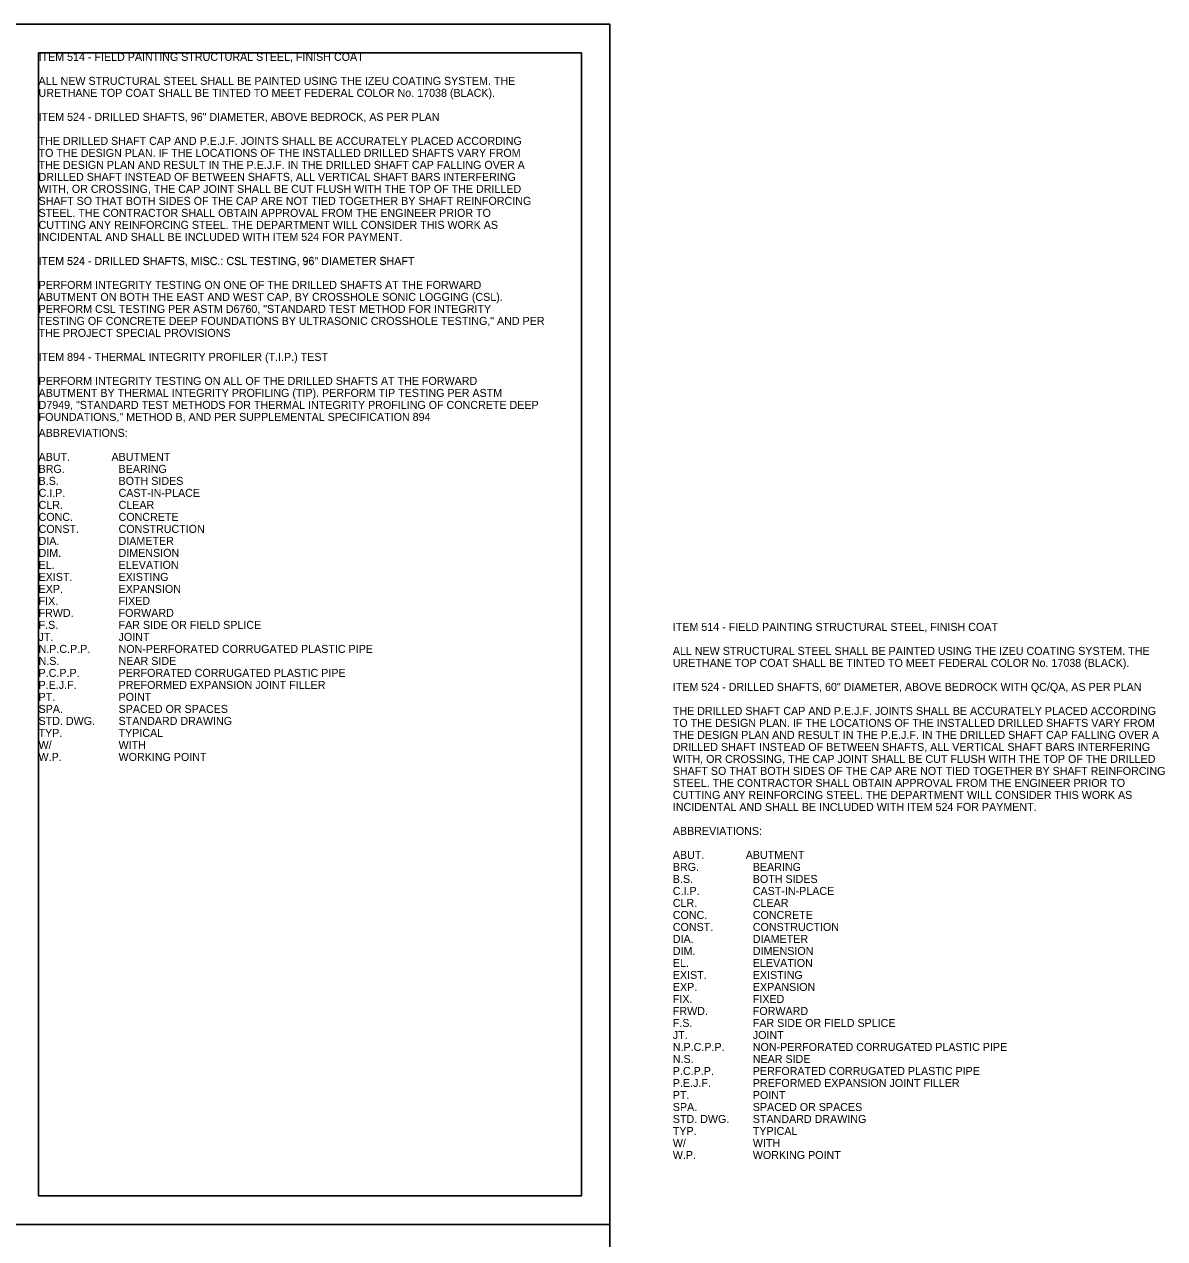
# Model space of a CAD drawing. Extents: x -27.4 to 41.5, y -43.2 to 24.4.
# Drawn here: x 21.49 to 41.45, y -1.99 to 19.26 of the extents above; entities that cross this region are included whole.
import ezdxf

# ---------------------------------------------------------------- set-up
doc = ezdxf.new("R2010")
doc.units = 0
for name, color, linetype in [('BR_P_Slab_Object', 7, 'Continuous'), ('BR_P_Sub_Foot_Hidden', 7, 'Continuous'), ('Default', 7, 'Continuous'), ('SH_Data', 7, 'Continuous')]:
    doc.layers.add(name, color=color, linetype=linetype)

msp = doc.modelspace()

# ---------------------------------------------------------------- linework, layer by layer
at = {"layer": 'BR_P_Slab_Object'}
msp.add_lwpolyline([(21.744, 18.759), (31.244, 18.759), (31.244, -1.241), (21.744, -1.241)], close=True, dxfattribs=at)
at = {"layer": 'SH_Data'}
for points in [[(1.244, 19.259), (31.744, 19.259), (31.744, -1.741), (1.244, -1.741)], [(1.244, -1.741), (31.744, -1.741), (31.744, -22.741), (1.244, -22.741)]]:
    msp.add_lwpolyline(points, close=True, dxfattribs=at)

# ---------------------------------------------------------------- texts
at = {"layer": 'BR_P_Sub_Foot_Hidden'}
for s, p in [('ITEM 514 - FIELD PAINTING STRUCTURAL STEEL, FINISH COAT', (21.744, 18.619)), ('ITEM 514 - FIELD PAINTING STRUCTURAL STEEL, FINISH COAT', (21.744, 18.619)), ('ALL NEW STRUCTURAL STEEL SHALL BE PAINTED USING THE IZEU COATING SYSTEM. THE ', (21.744, 18.199)), ('URETHANE TOP COAT SHALL BE TINTED TO MEET FEDERAL COLOR No. 17038 (BLACK).', (21.744, 17.989)), ('ITEM 524 - DRILLED SHAFTS, 96" DIAMETER, ABOVE BEDROCK, AS PER PLAN', (21.744, 17.569)), ('ITEM 524 - DRILLED SHAFTS, 96" DIAMETER, ABOVE BEDROCK, AS PER PLAN', (21.744, 17.569)), ('THE DRILLED SHAFT CAP AND P.E.J.F. JOINTS SHALL BE ACCURATELY PLACED ACCORDING ', (21.744, 17.149)), ('TO THE DESIGN PLAN. IF THE LOCATIONS OF THE INSTALLED DRILLED SHAFTS VARY FROM ', (21.744, 16.939)), ('THE DESIGN PLAN AND RESULT IN THE P.E.J.F. IN THE DRILLED SHAFT CAP FALLING OVER A ', (21.744, 16.729)), ('DRILLED SHAFT INSTEAD OF BETWEEN SHAFTS, ALL VERTICAL SHAFT BARS INTERFERING ', (21.744, 16.519)), ('WITH, OR CROSSING, THE CAP JOINT SHALL BE CUT FLUSH WITH THE TOP OF THE DRILLED ', (21.744, 16.309)), ('SHAFT SO THAT BOTH SIDES OF THE CAP ARE NOT TIED TOGETHER BY SHAFT REINFORCING ', (21.744, 16.099)), ('STEEL. THE CONTRACTOR SHALL OBTAIN APPROVAL FROM THE ENGINEER PRIOR TO ', (21.744, 15.889)), ('CUTTING ANY REINFORCING STEEL. THE DEPARTMENT WILL CONSIDER THIS WORK AS ', (21.744, 15.679)), ('INCIDENTAL AND SHALL BE INCLUDED WITH ITEM 524 FOR PAYMENT.', (21.744, 15.469)), ('ITEM 524 - DRILLED SHAFTS, MISC.: CSL TESTING, 96" DIAMETER SHAFT ', (21.744, 15.049)), ('PERFORM INTEGRITY TESTING ON ONE OF THE DRILLED SHAFTS AT THE FORWARD ', (21.744, 14.629)), ('ABUTMENT ON BOTH THE EAST AND WEST CAP, BY CROSSHOLE SONIC LOGGING (CSL). ', (21.744, 14.419)), ('PERFORM CSL TESTING PER ASTM D6760, "STANDARD TEST METHOD FOR INTEGRITY ', (21.744, 14.209)), ('TESTING OF CONCRETE DEEP FOUNDATIONS BY ULTRASONIC CROSSHOLE TESTING," AND PER ', (21.744, 13.999)), ('THE PROJECT SPECIAL PROVISIONS', (21.744, 13.789)), ('ITEM 894 - THERMAL INTEGRITY PROFILER (T.I.P.) TEST ', (21.744, 13.369)), ('PERFORM INTEGRITY TESTING ON ALL OF THE DRILLED SHAFTS AT THE FORWARD ', (21.744, 12.949)), ('ABUTMENT BY THERMAL INTEGRITY PROFILING (TIP). PERFORM TIP TESTING PER ASTM ', (21.744, 12.739)), ('D7949, "STANDARD TEST METHODS FOR THERMAL INTEGRITY PROFILING OF CONCRETE DEEP ', (21.744, 12.529)), ('FOUNDATIONS," METHOD B, AND PER SUPPLEMENTAL SPECIFICATION 894', (21.744, 12.319)), ('ABBREVIATIONS:', (21.744, 12.04)), ('ABUT.', (21.744, 11.62)), ('   ABUTMENT', (22.864, 11.62)), ('BRG.', (21.744, 11.41)), ('BEARING', (23.144, 11.41)), ('B.S.', (21.744, 11.2)), ('BOTH SIDES', (23.144, 11.2)), ('C.I.P.', (21.744, 10.99)), ('CAST-IN-PLACE', (23.144, 10.99)), ('CLR.', (21.744, 10.78)), ('CLEAR', (23.144, 10.78)), ('CONC.', (21.744, 10.57)), ('CONCRETE', (23.144, 10.57)), ('CONST. ', (21.744, 10.36)), ('CONSTRUCTION', (23.144, 10.36)), ('DIA.', (21.744, 10.15)), ('DIAMETER', (23.144, 10.15)), ('DIM.', (21.744, 9.94)), ('DIMENSION', (23.144, 9.94)), ('EL.', (21.744, 9.73)), ('ELEVATION', (23.144, 9.73)), ('EXIST.', (21.744, 9.52)), ('EXISTING', (23.144, 9.52)), ('EXP.', (21.744, 9.31)), ('EXPANSION', (23.144, 9.31)), ('FIX.', (21.744, 9.1)), ('FIXED', (23.144, 9.1)), ('FRWD.', (21.744, 8.89)), ('FORWARD', (23.144, 8.89)), ('F.S.', (21.744, 8.68)), ('FAR SIDE OR FIELD SPLICE', (23.144, 8.68)), ('ITEM 514 - FIELD PAINTING STRUCTURAL STEEL, FINISH COAT', (32.844, 8.645)), ('ITEM 514 - FIELD PAINTING STRUCTURAL STEEL, FINISH COAT', (32.844, 8.645)), ('JT.', (21.744, 8.47)), ('JOINT', (23.144, 8.47)), ('N.P.C.P.P.', (21.744, 8.26)), ('NON-PERFORATED CORRUGATED PLASTIC PIPE', (23.144, 8.26)), ('ALL NEW STRUCTURAL STEEL SHALL BE PAINTED USING THE IZEU COATING SYSTEM. THE ', (32.844, 8.225)), ('N.S.', (21.744, 8.05)), ('NEAR SIDE', (23.144, 8.05)), ('URETHANE TOP COAT SHALL BE TINTED TO MEET FEDERAL COLOR No. 17038 (BLACK).', (32.844, 8.015)), ('P.C.P.P.', (21.744, 7.84)), ('PERFORATED CORRUGATED PLASTIC PIPE', (23.144, 7.84)), ('P.E.J.F.', (21.744, 7.63)), ('PREFORMED EXPANSION JOINT FILLER', (23.144, 7.63)), ('ITEM 524 - DRILLED SHAFTS, 60" DIAMETER, ABOVE BEDROCK WITH QC/QA, AS PER PLAN', (32.844, 7.595)), ('ITEM 524 - DRILLED SHAFTS, 60" DIAMETER, ABOVE BEDROCK WITH QC/QA, AS PER PLAN', (32.844, 7.595)), ('PT.', (21.744, 7.42)), ('POINT', (23.144, 7.42)), ('SPA.', (21.744, 7.21)), ('SPACED OR SPACES', (23.144, 7.21)), ('THE DRILLED SHAFT CAP AND P.E.J.F. JOINTS SHALL BE ACCURATELY PLACED ACCORDING ', (32.844, 7.175)), ('STD. DWG.', (21.744, 7)), ('STANDARD DRAWING', (23.144, 7)), ('TO THE DESIGN PLAN. IF THE LOCATIONS OF THE INSTALLED DRILLED SHAFTS VARY FROM ', (32.844, 6.965)), ('TYP.', (21.744, 6.79)), ('TYPICAL', (23.144, 6.79)), ('THE DESIGN PLAN AND RESULT IN THE P.E.J.F. IN THE DRILLED SHAFT CAP FALLING OVER A ', (32.844, 6.755)), ('W/', (21.744, 6.58)), ('WITH', (23.144, 6.58)), ('DRILLED SHAFT INSTEAD OF BETWEEN SHAFTS, ALL VERTICAL SHAFT BARS INTERFERING ', (32.844, 6.545)), ('W.P.', (21.744, 6.37)), ('WORKING POINT', (23.144, 6.37)), ('WITH, OR CROSSING, THE CAP JOINT SHALL BE CUT FLUSH WITH THE TOP OF THE DRILLED ', (32.844, 6.335)), ('SHAFT SO THAT BOTH SIDES OF THE CAP ARE NOT TIED TOGETHER BY SHAFT REINFORCING ', (32.844, 6.125)), ('STEEL. THE CONTRACTOR SHALL OBTAIN APPROVAL FROM THE ENGINEER PRIOR TO ', (32.844, 5.915)), ('CUTTING ANY REINFORCING STEEL. THE DEPARTMENT WILL CONSIDER THIS WORK AS ', (32.844, 5.705)), ('INCIDENTAL AND SHALL BE INCLUDED WITH ITEM 524 FOR PAYMENT.', (32.844, 5.495)), ('ABBREVIATIONS:', (32.844, 5.075)), ('ABUT.', (32.844, 4.655)), ('   ABUTMENT', (33.964, 4.655)), ('BRG.', (32.844, 4.445)), ('BEARING', (34.244, 4.445)), ('B.S.', (32.844, 4.235)), ('BOTH SIDES', (34.244, 4.235)), ('C.I.P.', (32.844, 4.025)), ('CAST-IN-PLACE', (34.244, 4.025)), ('CLR.', (32.844, 3.815)), ('CLEAR', (34.244, 3.815)), ('CONC.', (32.844, 3.605)), ('CONCRETE', (34.244, 3.605)), ('CONST. ', (32.844, 3.395)), ('CONSTRUCTION', (34.244, 3.395)), ('DIA.', (32.844, 3.185)), ('DIAMETER', (34.244, 3.185)), ('DIM.', (32.844, 2.975)), ('DIMENSION', (34.244, 2.975)), ('EL.', (32.844, 2.765)), ('ELEVATION', (34.244, 2.765)), ('EXIST.', (32.844, 2.555)), ('EXISTING', (34.244, 2.555)), ('EXP.', (32.844, 2.345)), ('EXPANSION', (34.244, 2.345)), ('FIX.', (32.844, 2.135)), ('FIXED', (34.244, 2.135)), ('FRWD.', (32.844, 1.925)), ('FORWARD', (34.244, 1.925)), ('F.S.', (32.844, 1.715)), ('FAR SIDE OR FIELD SPLICE', (34.244, 1.715)), ('JT.', (32.844, 1.505)), ('JOINT', (34.244, 1.505)), ('N.P.C.P.P.', (32.844, 1.295)), ('NON-PERFORATED CORRUGATED PLASTIC PIPE', (34.244, 1.295)), ('N.S.', (32.844, 1.085)), ('NEAR SIDE', (34.244, 1.085)), ('P.C.P.P.', (32.844, 0.875)), ('PERFORATED CORRUGATED PLASTIC PIPE', (34.244, 0.875)), ('P.E.J.F.', (32.844, 0.665)), ('PREFORMED EXPANSION JOINT FILLER', (34.244, 0.665)), ('PT.', (32.844, 0.455)), ('POINT', (34.244, 0.455)), ('SPA.', (32.844, 0.245)), ('SPACED OR SPACES', (34.244, 0.245)), ('STD. DWG.', (32.844, 0.035)), ('STANDARD DRAWING', (34.244, 0.035)), ('TYP.', (32.844, -0.175)), ('TYPICAL', (34.244, -0.175)), ('W/', (32.844, -0.385)), ('WITH', (34.244, -0.385)), ('W.P.', (32.844, -0.595)), ('WORKING POINT', (34.244, -0.595))]:
    msp.add_text(s, height=0.14, dxfattribs=at).set_placement(p)
at = {"layer": 'Default'}
for s, p in [('ITEM 524 - DRILLED SHAFTS, MISC.: CSL TESTING, 96" DIAMETER SHAFT', (21.744, 15.045)), ('ITEM 894 - THERMAL INTEGRITY PROFILER (T.I.P.) TEST', (21.744, 13.369))]:
    msp.add_text(s, height=0.14, dxfattribs=at).set_placement(p)

doc.saveas('drawing.dxf')
